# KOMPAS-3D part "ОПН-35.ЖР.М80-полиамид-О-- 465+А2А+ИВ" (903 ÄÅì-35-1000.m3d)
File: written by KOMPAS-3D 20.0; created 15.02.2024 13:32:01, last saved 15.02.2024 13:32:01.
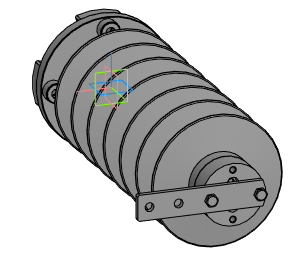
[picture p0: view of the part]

Document properties: Полное имя файла: C:\Users\drmla\OneDrive\Рабочий стол\ОПН\Модели\3 класс\002 353 01.m3d

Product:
- Part/product: ОПН-35.ЖР.М80-полиамид-О-- 465+А2А+ИВ

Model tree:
1. Операция без истории:1
2. Операция без истории:2
3. Операция без истории:3
4. Операция без истории:4
5. Операция без истории:5
6. Операция без истории:6
7. Операция без истории:7
8. Операция без истории:8
9. Операция без истории:9
10. Операция без истории:10
11. Операция без истории:11
12. Операция без истории:12
13. Операция без истории:13
14. Операция без истории:14
15. Операция без истории:15
16. Операция без истории:16
17. Операция без истории:17
18. Операция без истории:18
19. Операция без истории:19
20. Операция без истории:20
21. Операция без истории:21
22. Операция без истории:22
23. Операция без истории:23
24. Операция без истории:24
25. Операция без истории:25
26. Операция без истории:26
27. Операция без истории:27
28. Операция без истории:28
29. Операция без истории:29
30. Операция без истории:30
31. Операция без истории:31
32. Операция без истории:32
33. Операция без истории:33
34. Операция без истории:34
35. Операция без истории:35
36. Операция без истории:36
37. Операция без истории:37
38. Операция без истории:38
39. Операция без истории:39
40. Операция без истории:40
41. Операция без истории:41
42. Операция без истории:42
